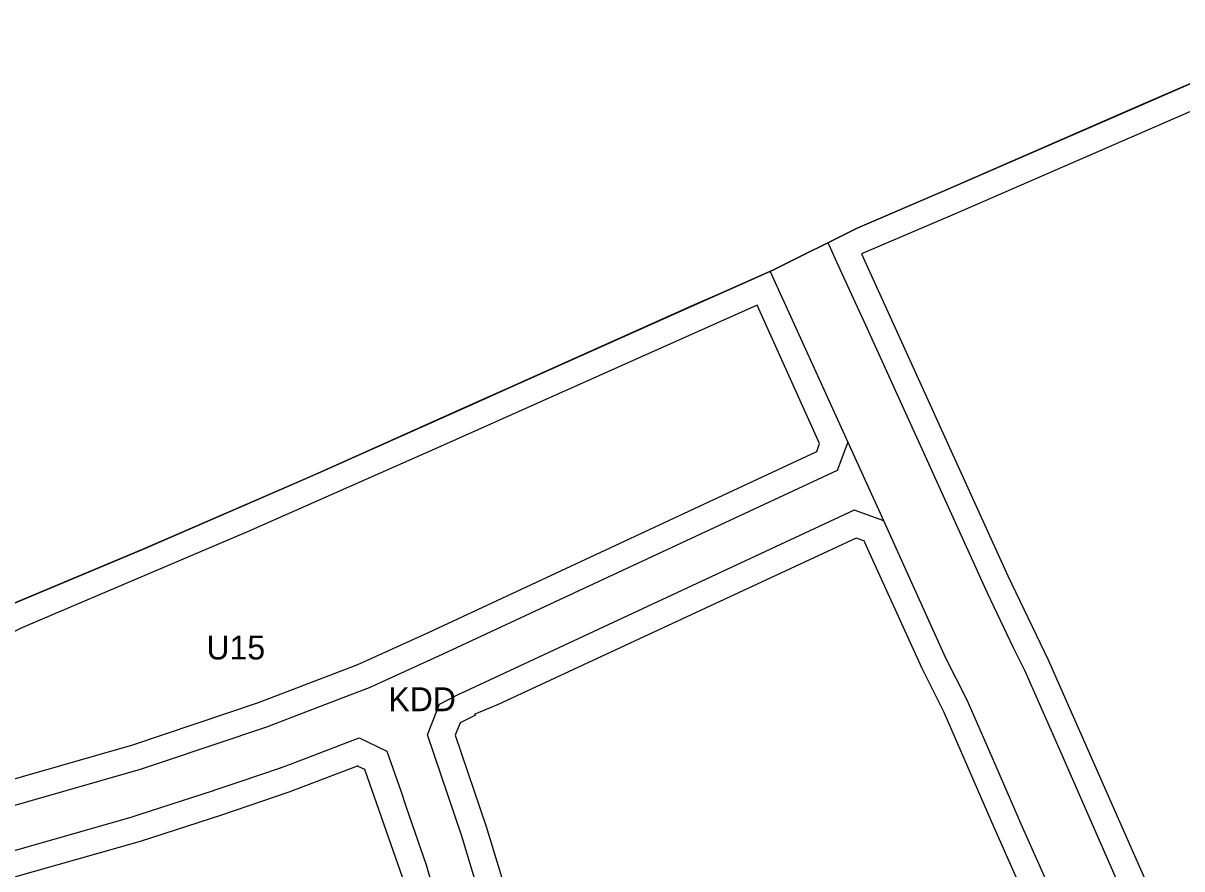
# Model space of a CAD drawing. Extents: x 7428103 to 7431580, y 5545880 to 5549002.
# Drawn here: x 7428821 to 7429089.8, y 5548288 to 5548484.3 of the extents above; entities that cross this region are included whole.
import ezdxf

# ---------------------------------------------------------------- set-up
doc = ezdxf.new("R2010")
doc.units = 0
for name, color, linetype in [('CZ_L_granica obszaru objętego planem', 7, 'Continuous'), ('CZ_L_linie rozgraniczające tereny o różnym przeznaczeniu oraz różnych warunkach ich zabudowy i zagospodarowania', 7, 'Continuous'), ('CZ_L_maksymalne nieprzekraczalne linie zabudowy', 7, 'Continuous'), ('CZ_L_opisy_linie rozgraniczające tereny o różnym przeznaczeniu oraz różnych warunkach ich zabudowy i zagospodarowania', 7, 'Continuous')]:
    doc.layers.add(name, color=color, linetype=linetype)

msp = doc.modelspace()

# ---------------------------------------------------------------- linework, layer by layer
at = {"layer": 'CZ_L_granica obszaru objętego planem'}
for p, q in [((7429079.07, 5548464.83), (7429123.84, 5548484.34)), ((7429034.73, 5548445.52), (7429079.07, 5548464.83)), ((7429014.6, 5548436.86), (7429034.73, 5548445.52)), ((7428994.99, 5548427.11), (7429014.6, 5548436.86)), ((7428981.97, 5548421.31), (7428994.99, 5548427.11)), ((7428932.08, 5548399.02), (7428977.47, 5548419.31)), ((7428977.47, 5548419.31), (7428981.97, 5548421.31)), ((7428926.61, 5548396.57), (7428932.08, 5548399.02)), ((7428890.73, 5548380.53), (7428926.61, 5548396.57)), ((7428849.1, 5548362.4), (7428886.15, 5548378.53)), ((7428886.15, 5548378.53), (7428890.73, 5548380.53)), ((7428818.46, 5548349.55), (7428849.1, 5548362.4))]:
    msp.add_line(p, q, dxfattribs=at)
at = {"layer": 'CZ_L_linie rozgraniczające tereny o różnym przeznaczeniu oraz różnych warunkach ich zabudowy i zagospodarowania'}
for p, q in [((7429007.73, 5548433.33), (7429008.01, 5548432.7)), ((7429008.01, 5548432.7), (7429010.12, 5548428.08)), ((7429010.12, 5548428.08), (7429014.51, 5548418.46)), ((7428994.33, 5548426.7), (7429012.32, 5548387.05)), ((7429014.51, 5548418.46), (7429016.4, 5548414.31)), ((7429016.4, 5548414.31), (7429017.9, 5548411.03)), ((7429017.9, 5548411.03), (7429029.48, 5548385.54)), ((7429012.32, 5548387.05), (7429009.87, 5548380.49)), ((7429012.32, 5548387.05), (7429020.58, 5548368.86)), ((7429029.48, 5548385.54), (7429044.74, 5548351.93)), ((7429009.87, 5548380.49), (7428918.23, 5548337.8)), ((7428922.44, 5548328.73), (7429013.92, 5548371.35)), ((7429013.92, 5548371.35), (7429013.99, 5548371.31)), ((7429013.99, 5548371.31), (7429020.58, 5548368.86)), ((7429020.58, 5548368.86), (7429035.02, 5548337.03)), ((7429044.74, 5548351.93), (7429050.6, 5548339.57)), ((7429050.6, 5548339.57), (7429053.32, 5548334.12)), ((7428918.23, 5548337.8), (7428901.24, 5548330.03)), ((7429035.02, 5548337.03), (7429039.94, 5548327.31)), ((7429053.32, 5548334.12), (7429061.43, 5548315.77)), ((7428895.13, 5548327.7), (7428880.43, 5548322.08)), ((7428901.24, 5548330.03), (7428895.13, 5548327.7)), ((7428917.61, 5548326.27), (7428921.9, 5548328.49)), ((7428921.9, 5548328.49), (7428922.41, 5548328.72)), ((7428922.41, 5548328.72), (7428922.42, 5548328.73)), ((7428922.42, 5548328.73), (7428922.44, 5548328.73)), ((7428914.78, 5548319.18), (7428917.61, 5548326.27)), ((7429039.94, 5548327.31), (7429044.39, 5548317.25)), ((7428880.43, 5548322.08), (7428877.44, 5548320.94)), ((7428877.44, 5548320.94), (7428852.79, 5548312.64)), ((7428882.99, 5548312.36), (7428898.96, 5548318.46)), ((7428898.96, 5548318.46), (7428905.4, 5548315.35)), ((7428922.77, 5548295.64), (7428914.78, 5548319.18)), ((7429044.39, 5548317.25), (7429051.79, 5548300.08)), ((7428905.4, 5548315.35), (7428908.58, 5548306.16)), ((7429061.43, 5548315.77), (7429070.99, 5548294)), ((7428852.79, 5548312.64), (7428848.13, 5548311.07)), ((7428871.35, 5548308.34), (7428880.73, 5548311.5)), ((7428880.73, 5548311.5), (7428880.88, 5548311.56)), ((7428880.88, 5548311.56), (7428880.92, 5548311.56)), ((7428880.92, 5548311.56), (7428882.99, 5548312.36)), ((7428848.13, 5548311.07), (7428821.98, 5548303.59)), ((7428847.87, 5548300.62), (7428865.18, 5548306.26)), ((7428865.18, 5548306.26), (7428865.24, 5548306.2)), ((7428865.24, 5548306.2), (7428865.29, 5548306.3)), ((7428865.29, 5548306.3), (7428871.35, 5548308.34)), ((7428908.58, 5548306.16), (7428909.81, 5548302.57)), ((7428821.98, 5548303.59), (7428813.82, 5548301.26)), ((7428846.31, 5548300.11), (7428847.87, 5548300.62)), ((7428909.81, 5548302.57), (7428913.26, 5548292.55)), ((7428826.02, 5548294.35), (7428846.26, 5548300.14)), ((7428846.26, 5548300.14), (7428846.31, 5548300.11)), ((7429051.79, 5548300.08), (7429052.19, 5548299.2)), ((7429052.19, 5548299.2), (7429077.97, 5548241.08)), ((7428927.78, 5548279.14), (7428922.77, 5548295.64)), ((7428816.49, 5548291.62), (7428826.02, 5548294.35)), ((7428913.26, 5548292.55), (7428914.49, 5548288.97)), ((7429070.99, 5548294), (7429083, 5548266.72)), ((7428914.49, 5548288.97), (7428917.33, 5548279.27))]:
    msp.add_line(p, q, dxfattribs=at)
msp.add_lwpolyline([(7429123.85, 5548484.23), (7429079.08, 5548464.72), (7429034.74, 5548445.41), (7429014.61, 5548436.76), (7428995.01, 5548427), (7428981.98, 5548421.2), (7428977.48, 5548419.2), (7428932.1, 5548398.91), (7428926.62, 5548396.46), (7428890.75, 5548380.42), (7428886.16, 5548378.42), (7428849.11, 5548362.29), (7428818.48, 5548349.44)], dxfattribs=at)
at = {"layer": 'CZ_L_maksymalne nieprzekraczalne linie zabudowy'}
for points in [[(7429115.1, 5548473.99), (7429037.11, 5548440.01), (7429015.52, 5548430.78), (7429049.45, 5548356.05), (7429058.81, 5548336.55), (7429096.56, 5548250.96), (7429126.15, 5548245.63), (7429130.98, 5548244.54)], [(7429005.8, 5548386.74), (7428991.29, 5548418.89), (7428917.1, 5548385.74), (7428873.16, 5548366.33), (7428820.69, 5548343.95), (7428769.64, 5548318.32), (7428766.98, 5548316.11), (7428767.78, 5548299.51)], [(7428783.74, 5548300.14), (7428789.56, 5548301.39), (7428812.38, 5548307.09), (7428846.47, 5548316.85), (7428875.61, 5548326.67), (7428898.63, 5548335.46), (7428915.02, 5548342.93), (7429005.13, 5548384.94), (7429005.8, 5548386.74)], [(7429016.26, 5548364.07), (7429014.27, 5548364.81), (7428931.18, 5548326.18), (7428925.61, 5548323.9)], [(7429084.76, 5548226.4), (7429080.39, 5548228.73), (7429079.19, 5548229.7), (7429075.93, 5548233.22), (7429072.53, 5548238.56), (7429046.32, 5548297.62), (7429034.68, 5548324.36), (7429029.58, 5548334.52), (7429016.22, 5548363.96)], [(7428925.96, 5548323.75), (7428922.37, 5548321.96), (7428921.24, 5548319.04), (7428928.4, 5548297.84), (7428933.65, 5548280.58), (7428952.4, 5548217), (7428958.03, 5548214.44), (7428961.75, 5548202.28)], [(7428898.72, 5548311.94), (7428882.64, 5548305.81), (7428867.03, 5548300.47), (7428848.12, 5548294.4), (7428818.13, 5548285.85), (7428805.17, 5548282.55), (7428803.78, 5548280.38), (7428803.68, 5548279.86), (7428814.27, 5548192.52)], [(7428898.63, 5548311.9), (7428900.15, 5548311.14), (7428909.02, 5548285.99), (7428931.19, 5548211), (7428928.46, 5548205.68), (7428931.11, 5548196.13)]]:
    msp.add_lwpolyline(points, dxfattribs=at)

# ---------------------------------------------------------------- texts
at = {"layer": 'CZ_L_opisy_linie rozgraniczające tereny o różnym przeznaczeniu oraz różnych warunkach ich zabudowy i zagospodarowania'}
for s, p in [('U15', (7428863.52, 5548336.64)), ('KDD', (7428905.73, 5548324.63))]:
    msp.add_text(s, height=5.549, dxfattribs=at).set_placement(p)

doc.saveas('drawing.dxf')
